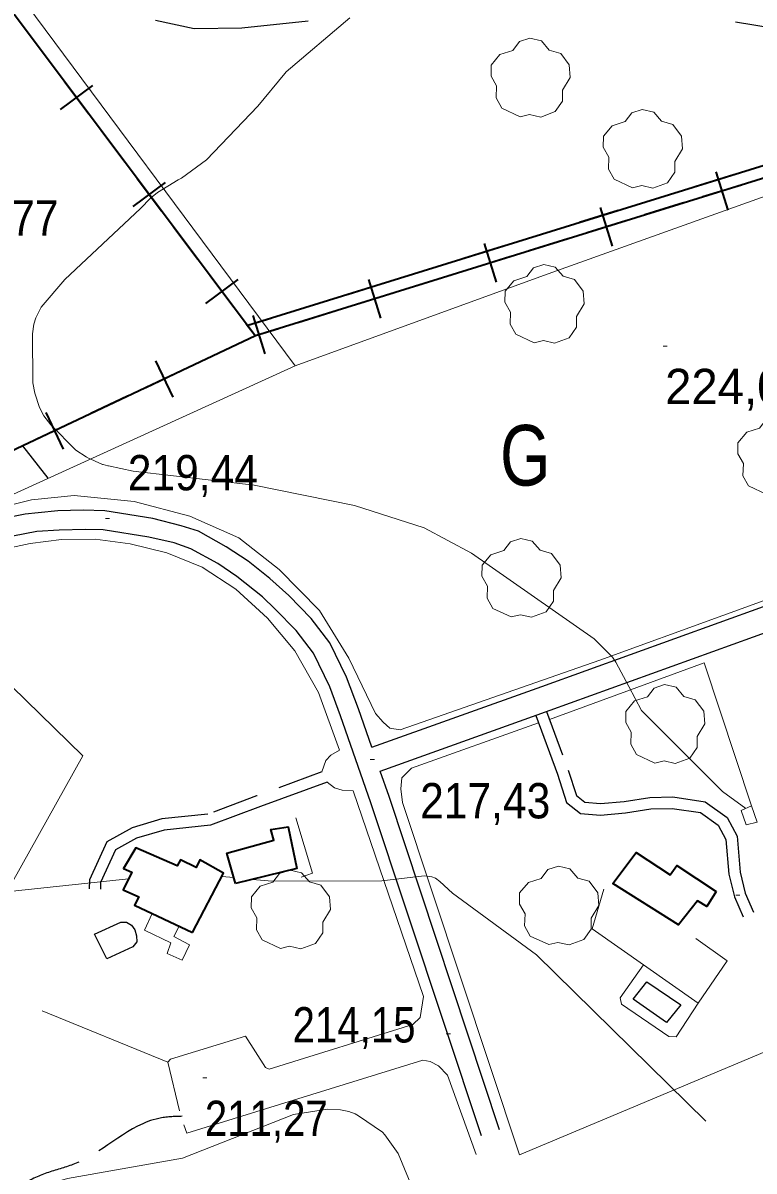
# Model space of a CAD drawing. Extents: x 480269 to 484877, y 4383588 to 4386804.
# Drawn here: x 482664.5 to 482845.4, y 4384938.2 to 4385222.5 of the extents above; entities that cross this region are included whole.
import ezdxf
from ezdxf.enums import TextEntityAlignment as Align

# ---------------------------------------------------------------- set-up
doc = ezdxf.new("R2010")
doc.units = 0
doc.header["$LTSCALE"] = 3.8
doc.linetypes.add('LONG_DASHED', pattern=[7.5, 6, -1.5])
doc.linetypes.add('MEDIUM_DASHED', pattern=[4.5, 3, -1.5])
for name, color, linetype, lineweight in [('21', 7, 'Continuous', 25), ('25', 7, 'LONG_DASHED', 25), ('27', 7, 'Continuous', 25), ('29', 7, 'Continuous', 13), ('34', 7, 'Continuous', 35), ('37', 7, 'Continuous', 25), ('38', 7, 'Continuous', 25), ('47', 7, 'Continuous', 35), ('51', 7, 'Continuous', 13), ('7', 7, 'Continuous', 13), ('9', 7, 'Continuous', 13)]:
    doc.layers.add(name, color=color, linetype=linetype, lineweight=lineweight)
doc.layers.add('31', color=7, linetype='Continuous')

msp = doc.modelspace()

# ---------------------------------------------------------------- linework, layer by layer
at = {"layer": '21'}
for points in [[(482685.28, 4384990.76), (482682.2, 4384996.9), (482688.72, 4384999.82), (482690.15, 4384999.83), (482691.37, 4384999.12), (482692.2, 4384997.92), (482692.63, 4384996.44), (482692.69, 4384995), (482691.71, 4384993.76), (482691.67, 4384993.76)], [(482815.5, 4384980.83), (482818.82, 4384985.11), (482827.28, 4384979.37), (482823.72, 4384975.04)]]:
    msp.add_lwpolyline(points, close=True, dxfattribs=at)
at = {"layer": '25'}
msp.add_lwpolyline([(482586.91, 4385220.21), (482629.4, 4385162.78), (482670.68, 4385109.75)], dxfattribs=at)
at = {"layer": '27'}
msp.add_spline([(482987.06, 4385196.22), (482962.01, 4385203.27), (482933.82, 4385208.75), (482918.16, 4385210.32), (482910.33, 4385217.37), (482911.12, 4385227.55), (482911.12, 4385236.17), (482900.16, 4385244), (482857.87, 4385258.89), (482836.73, 4385270.64), (482824.21, 4385265.15), (482832.82, 4385247.14), (482820.29, 4385239.3), (482767.05, 4385239.3), (482715.37, 4385240.87), (482694.23, 4385249.49), (482675.44, 4385265.94), (482679.36, 4385287.09), (482678.57, 4385302.75), (482650.39, 4385311.37), (482636.29, 4385330.17), (482633.95, 4385351.32), (482617.5, 4385368.55), (482588.53, 4385379.52), (482572.87, 4385393.62), (482558.78, 4385411.63), (482539.21, 4385429.65), (482525.9, 4385448.45), (482516.5, 4385468.82), (482492.23, 4385501.72), (482482.83, 4385522.08), (482488.31, 4385537.75), (482533.73, 4385569.87), (482542.34, 4385576.13)], degree=3, dxfattribs=at)
at = {"layer": '29'}
for points in [[(482787.53, 4385199.25), (482782.99, 4385201.37), (482781.58, 4385203.91), (482781.68, 4385206.89), (482780.31, 4385209.3), (482780.35, 4385212.05), (482782.51, 4385214.65), (482785.7, 4385215.65), (482787.35, 4385217.84), (482789.92, 4385218.67), (482792.78, 4385218.02), (482794.73, 4385215.75), (482797.54, 4385214.93), (482799.67, 4385212.08), (482799.91, 4385208.95), (482798.03, 4385205.8), (482798.03, 4385203.12), (482796.21, 4385200.51), (482792.59, 4385199.17), (482789.82, 4385199.8)], [(482815.31, 4385181.64), (482810.77, 4385183.76), (482809.36, 4385186.3), (482809.46, 4385189.28), (482808.09, 4385191.69), (482808.13, 4385194.44), (482810.29, 4385197.04), (482813.48, 4385198.04), (482815.13, 4385200.23), (482817.7, 4385201.06), (482820.56, 4385200.41), (482822.51, 4385198.14), (482825.32, 4385197.32), (482827.45, 4385194.47), (482827.69, 4385191.34), (482825.81, 4385188.19), (482825.81, 4385185.51), (482823.99, 4385182.9), (482820.37, 4385181.56), (482817.6, 4385182.19)], [(482790.96, 4385143.27), (482786.42, 4385145.39), (482785.01, 4385147.93), (482785.11, 4385150.91), (482783.74, 4385153.32), (482783.78, 4385156.07), (482785.94, 4385158.67), (482789.13, 4385159.67), (482790.78, 4385161.86), (482793.35, 4385162.69), (482796.21, 4385162.04), (482798.16, 4385159.77), (482800.97, 4385158.95), (482803.1, 4385156.1), (482803.34, 4385152.97), (482801.46, 4385149.82), (482801.46, 4385147.14), (482799.64, 4385144.53), (482796.02, 4385143.19), (482793.25, 4385143.82)], [(482848.58, 4385105.73), (482844.04, 4385107.85), (482842.63, 4385110.39), (482842.73, 4385113.37), (482841.36, 4385115.78), (482841.4, 4385118.53), (482843.56, 4385121.13), (482846.75, 4385122.13), (482848.4, 4385124.32), (482850.97, 4385125.15), (482853.83, 4385124.5), (482855.78, 4385122.23), (482858.59, 4385121.41), (482860.72, 4385118.56), (482860.96, 4385115.43), (482859.08, 4385112.28), (482859.08, 4385109.6), (482857.26, 4385106.99), (482853.64, 4385105.65), (482850.87, 4385106.28)], [(482785.27, 4385075.43), (482780.73, 4385077.55), (482779.32, 4385080.09), (482779.42, 4385083.07), (482778.05, 4385085.48), (482778.09, 4385088.23), (482780.25, 4385090.83), (482783.44, 4385091.83), (482785.09, 4385094.02), (482787.66, 4385094.85), (482790.52, 4385094.2), (482792.47, 4385091.93), (482795.28, 4385091.11), (482797.41, 4385088.26), (482797.65, 4385085.13), (482795.77, 4385081.98), (482795.77, 4385079.3), (482793.95, 4385076.69), (482790.33, 4385075.35), (482787.56, 4385075.98)], [(482820.84, 4385039.24), (482816.3, 4385041.36), (482814.89, 4385043.9), (482814.99, 4385046.88), (482813.62, 4385049.29), (482813.66, 4385052.04), (482815.82, 4385054.64), (482819.01, 4385055.64), (482820.66, 4385057.83), (482823.23, 4385058.66), (482826.09, 4385058.01), (482828.04, 4385055.74), (482830.85, 4385054.92), (482832.98, 4385052.07), (482833.22, 4385048.94), (482831.34, 4385045.79), (482831.34, 4385043.11), (482829.52, 4385040.5), (482825.9, 4385039.16), (482823.13, 4385039.79)], [(482794.57, 4384994.29), (482790.03, 4384996.41), (482788.62, 4384998.95), (482788.72, 4385001.93), (482787.35, 4385004.34), (482787.39, 4385007.09), (482789.55, 4385009.69), (482792.74, 4385010.69), (482794.39, 4385012.88), (482796.96, 4385013.71), (482799.82, 4385013.06), (482801.77, 4385010.79), (482804.58, 4385009.97), (482806.71, 4385007.12), (482806.95, 4385003.99), (482805.07, 4385000.84), (482805.07, 4384998.16), (482803.25, 4384995.55), (482799.63, 4384994.21), (482796.86, 4384994.84)], [(482728.19, 4384993.33), (482723.65, 4384995.45), (482722.24, 4384997.99), (482722.34, 4385000.97), (482720.97, 4385003.38), (482721.01, 4385006.13), (482723.17, 4385008.73), (482726.36, 4385009.73), (482728.01, 4385011.92), (482730.58, 4385012.75), (482733.44, 4385012.1), (482735.39, 4385009.83), (482738.2, 4385009.01), (482740.33, 4385006.16), (482740.57, 4385003.03), (482738.69, 4384999.88), (482738.69, 4384997.2), (482736.87, 4384994.59), (482733.25, 4384993.25), (482730.48, 4384993.88)]]:
    msp.add_lwpolyline(points, close=True, dxfattribs=at)
at = {"layer": '34'}
for p, q in [((482665.77, 4385220.01), (482671.77, 4385212.01)), ((482673.76, 4385201.01), (482681.77, 4385207)), ((482674.77, 4385208), (482680.76, 4385200)), ((482683.76, 4385196), (482689.76, 4385188)), ((482692.76, 4385184), (482698.76, 4385176)), ((482840.39, 4385184.9), (482830.84, 4385181.94)), ((482840.39, 4385184.9), (482830.84, 4385181.94)), ((482838.98, 4385176.1), (482836.01, 4385185.65)), ((482691.76, 4385177), (482699.76, 4385183)), ((482842.27, 4385182.35), (482832.72, 4385179.39)), ((482827.95, 4385177.91), (482818.4, 4385174.94)), ((482811.75, 4385176.01), (482802.2, 4385173.04)), ((482811.75, 4385176.01), (482802.2, 4385173.04)), ((482810.34, 4385167.2), (482807.37, 4385176.75)), ((482813.63, 4385173.46), (482804.08, 4385170.49)), ((482701.76, 4385172), (482707.76, 4385164)), ((482783.11, 4385167.11), (482773.56, 4385164.15)), ((482783.11, 4385167.11), (482773.56, 4385164.15)), ((482781.7, 4385158.31), (482778.73, 4385167.86)), ((482799.31, 4385169.01), (482789.76, 4385166.04)), ((482784.99, 4385164.56), (482775.44, 4385161.6)), ((482709.75, 4385153), (482717.76, 4385159)), ((482710.76, 4385160), (482716.75, 4385152)), ((482754.47, 4385158.22), (482744.92, 4385155.25)), ((482754.47, 4385158.22), (482744.92, 4385155.25)), ((482753.06, 4385149.41), (482750.09, 4385158.96)), ((482770.67, 4385160.11), (482761.12, 4385157.15)), ((482756.35, 4385155.67), (482746.8, 4385152.7)), ((482725.83, 4385149.32), (482720.12, 4385147.55)), ((482725.83, 4385149.32), (482720.12, 4385147.55)), ((482724.42, 4385140.52), (482721.45, 4385150.07)), ((482742.03, 4385151.22), (482732.48, 4385148.25)), ((482719.75, 4385148), (482722, 4385145)), ((482727.71, 4385146.77), (482722, 4385145)), ((482717.48, 4385142.86), (482708.44, 4385138.59)), ((482697.26, 4385138.83), (482701.54, 4385129.79)), ((482703.92, 4385136.45), (482694.88, 4385132.18)), ((482690.36, 4385130.04), (482681.32, 4385125.77)), ((482670.14, 4385126.01), (482674.41, 4385116.97)), ((482676.8, 4385123.63), (482667.76, 4385119.35))]:
    msp.add_line(p, q, dxfattribs=at)
for points in [[(481732.67, 4386453.74), (481770, 4386403), (482108, 4385964), (482722, 4385145)], [(483464.12, 4384844.55), (483013.12, 4385238.55), (482720.12, 4385147.55)], [(483464.12, 4384844.55), (483013.12, 4385238.55), (482720.12, 4385147.55)], [(483466, 4384842), (483015, 4385236), (482722, 4385145)], [(482722, 4385145), (482428, 4385006), (482209, 4384913), (481448, 4384699), (481251, 4384637), (481013, 4384577), (480976, 4384524), (480944, 4384410), (480887.47, 4384143.52)]]:
    msp.add_lwpolyline(points, dxfattribs=at)
at = {"layer": '37'}
for points in [[(482750.83, 4385043.15), (482792.84, 4385058.2), (482913.56, 4385101.78), (482939.57, 4385111.12), (482955.6, 4385115), (482967.37, 4385116.08), (482975.61, 4385116.03), (482978.44, 4385115.95), (482985.74, 4385115.14), (482992.89, 4385114), (482999.97, 4385112.36), (483004.37, 4385110.93), (483011.65, 4385108.69), (483016.47, 4385106.74), (483023.56, 4385103.12), (483028.35, 4385099.96), (483040.15, 4385090.7), (483056.73, 4385076.2), (483085.09, 4385052.01)], [(482752.89, 4385037.24), (482794.96, 4385052.31), (482915.68, 4385095.89), (482941.37, 4385105.12), (482956.63, 4385108.81), (482967.62, 4385109.83), (482975.06, 4385109.91), (482977.98, 4385109.7), (482985.07, 4385109.02), (482991.66, 4385107.85), (483002.53, 4385104.94), (483013.88, 4385101.02), (483019.88, 4385097.89), (483024.85, 4385094.76), (483036.16, 4385085.88), (483052.64, 4385071.47), (483081.03, 4385047.25)], [(482750.83, 4385043.15), (482747.52, 4385052.71), (482744.53, 4385060.52), (482740.43, 4385068.99), (482735.77, 4385075.02), (482730.27, 4385080.73), (482725.6, 4385084.97), (482720.22, 4385089.27), (482714.78, 4385092.76), (482707.89, 4385096.67), (482703.64, 4385097.96), (482696.65, 4385099.78), (482684.74, 4385101.71), (482679.41, 4385101.85), (482673.14, 4385101.65), (482668.27, 4385101.21), (482665.02, 4385100.88), (482660.89, 4385100.07)], [(482777.93, 4384946.98), (482750.57, 4385029.42), (482743.09, 4385050.98), (482740.42, 4385058.13), (482736.37, 4385066.43), (482732.09, 4385072.09), (482726.92, 4385077.35), (482723.76, 4385080.43), (482717.45, 4385085.4), (482712.73, 4385088.65), (482706, 4385092.27), (482701.91, 4385093.74), (482695.63, 4385095.13), (482684.37, 4385096.96), (482679.95, 4385097.09), (482673.46, 4385096.91), (482667.94, 4385096.55), (482662.02, 4385095.42)], [(482782.44, 4384948.48), (482755.07, 4385030.94), (482752.89, 4385037.24)]]:
    msp.add_lwpolyline(points, dxfattribs=at)
at = {"layer": '38'}
for points in [[(482888.85, 4385225.44), (482873.65, 4385220.93), (482858.45, 4385219.79), (482840.77, 4385222.66)], [(482735.08, 4385222.93), (482718.69, 4385221.15), (482706.82, 4385220.99), (482697.27, 4385223.12)], [(482791.36, 4385051.02), (482796.74, 4385036.53), (482798.97, 4385029.5), (482802.43, 4385026.8), (482807.39, 4385026.35), (482813.59, 4385026.89), (482819.82, 4385027.92), (482825.14, 4385028), (482832.17, 4385026.97), (482836.51, 4385023.87), (482838.43, 4385020.34), (482839.13, 4385011.77), (482840.51, 4385006.09), (482842.65, 4385001.21)], [(482739.79, 4385034.55), (482723.28, 4385028.5), (482710.87, 4385023.85), (482699.4, 4385022.64), (482692.62, 4385020.62), (482687.39, 4385017.73), (482683.71, 4385009.65), (482683.65, 4385008.04)]]:
    msp.add_lwpolyline(points, dxfattribs=at)
at = {"layer": '38', "linetype": 'MEDIUM_DASHED'}
for points in [[(482794.03, 4385051.98), (482799.43, 4385037.46), (482801.42, 4385031.2), (482803.52, 4385029.55), (482807.39, 4385029.2), (482813.24, 4385029.71), (482819.56, 4385030.75), (482825.32, 4385030.85), (482833.26, 4385029.68), (482838.7, 4385025.8), (482841.21, 4385021.17), (482841.95, 4385012.22), (482843.21, 4385007), (482845.25, 4385002.36)], [(482738.47, 4385037.05), (482722.31, 4385031.13), (482710.22, 4385026.59), (482698.85, 4385025.4), (482691.53, 4385023.22), (482685.22, 4385019.73), (482680.93, 4385010.3), (482680.85, 4385008.14)]]:
    msp.add_lwpolyline(points, dxfattribs=at)
at = {"layer": '38', "linetype": 'LONG_DASHED'}
msp.add_spline([(482703.9, 4384951.8), (482698.11, 4384951.28), (482678.04, 4384940.33), (482671.68, 4384938.18), (482665.31, 4384935.39), (482661.35, 4384932.1), (482655.82, 4384925.86), (482650.14, 4384918.86), (482644.15, 4384906.93), (482643.07, 4384904.68), (482639.1, 4384898.05), (482634.64, 4384889.99), (482631.91, 4384884.65), (482627.67, 4384878.99), (482625.53, 4384876.32)], degree=3, dxfattribs=at)
at = {"layer": '47', "lineweight": 13}
msp.add_lwpolyline([(482846.12, 4385024.59), (482843.4, 4385023.99), (482842.23, 4385027.51), (482844.76, 4385028.62)], close=True, dxfattribs=at)
at = {"layer": '47'}
for points in [[(482717.11, 4385009.39), (482714.93, 4385016.95), (482726.56, 4385020.2), (482725.83, 4385022.78), (482730.09, 4385023.44), (482732.24, 4385013.14)], [(482706.48, 4384997.26), (482714.08, 4385011.96), (482708.27, 4385015.29), (482707.38, 4385013.42), (482703.45, 4385015.33), (482702.64, 4385013.81), (482692.46, 4385018.22), (482689.35, 4385013.14), (482691.44, 4385012.27), (482689.27, 4385007.9), (482693.13, 4385006.14), (482692.11, 4385004.08)], [(482836.04, 4385007.46), (482833.66, 4385003.72), (482831.36, 4385005.13), (482826.66, 4384999.16), (482810.44, 4385009.47), (482816.22, 4385017.11), (482824.61, 4385011.61), (482826.3, 4385013.89)]]:
    msp.add_lwpolyline(points, close=True, dxfattribs=at)
at = {"layer": '51'}
msp.add_line((482700.32, 4384965.17), (482669.22, 4384977.94), dxfattribs=at)
for points in [[(482404.1, 4385677.73), (482302.92, 4385714.75), (482302.94, 4385713.84), (482359.86, 4385638.29), (482423.37, 4385556.01), (482487.7, 4385471.02), (482548.28, 4385389.71), (482609.6, 4385302.12), (482658.45, 4385236.36), (482731.86, 4385137.6), (482793.32, 4385159.98), (482893.05, 4385195.69), (482991.91, 4385230.66), (483071.52, 4385260.62), (483095.48, 4385269.3)], [(482942.5, 4385213.18), (482977.38, 4385117.59), (482963.03, 4385117.44), (482951.62, 4385115.72), (482942.17, 4385113.17), (482923.87, 4385106.77), (482898.56, 4385097.91), (482807.23, 4385064.72), (482757.84, 4385047.5), (482755.28, 4385047.9), (482753.59, 4385049.34), (482751.71, 4385051.55), (482745.16, 4385065.2), (482737.85, 4385077), (482727.91, 4385087.2), (482717.9, 4385095.04), (482705.8, 4385100.41), (482691.98, 4385104.02), (482677.18, 4385105.47), (482666.61, 4385104.38), (482649.93, 4385100.31), (482731.86, 4385137.6)], [(482738.47, 4385037.05), (482739.42, 4385039.88), (482740.69, 4385041.24), (482742.85, 4385042.4), (482737.61, 4385056.68), (482731.73, 4385067.03), (482724.98, 4385075.1), (482717.14, 4385082.31), (482708.84, 4385087.77), (482700.06, 4385091.3), (482691.02, 4385093.51), (482682.36, 4385094.64), (482674.01, 4385094.58), (482666.31, 4385093.62), (482658.93, 4385092.06)], [(482637.01, 4385082.27), (482679.29, 4385041.06), (482648.64, 4384986.12), (482603.01, 4384903.74), (482627.65, 4384884.94)], [(482844.76, 4385028.62), (482833.04, 4385064.09), (482794.76, 4385050.01)], [(482792.04, 4385049.2), (482760.65, 4385037.97), (482758.22, 4385035.58), (482757.98, 4385032.85), (482758.41, 4385029.52), (482787.36, 4384942.24), (482862.97, 4384974.04), (482897.59, 4384990.73)], [(482739.79, 4385034.55), (482741.6, 4385033.08), (482743.47, 4385032.52), (482746.2, 4385032.34), (482763.58, 4384981.45), (482762.74, 4384976.28), (482760.97, 4384974.5), (482725.44, 4384963.48), (482724.49, 4384963.89), (482719.58, 4384971.63), (482700.98, 4384965.91), (482700.32, 4384965.17), (482703.22, 4384953.14)], [(482733.34, 4385010.98), (482736.17, 4385011.98), (482732.04, 4385025.71)], [(482808.18, 4385008.03), (482805.29, 4384998.23), (482831.59, 4384979.78), (482838.72, 4384990.3), (482830.99, 4384995.81)], [(482696.46, 4385002.03), (482694.54, 4384997.9), (482701.06, 4384994.78), (482700.21, 4384992.12), (482703.87, 4384990.48), (482705.68, 4384994.21), (482701.86, 4384996.33), (482703.16, 4384998.85)], [(482831.59, 4384979.78), (482826.11, 4384971.45), (482824.28, 4384971.56), (482812.58, 4384979.52), (482812.24, 4384981.12), (482817.99, 4384989.33)], [(482704.3, 4384949.72), (482705.04, 4384947.6), (482763.46, 4384965.68), (482765.28, 4384965.35), (482767.33, 4384964.26), (482769.57, 4384961.94), (482776.6, 4384942.3)]]:
    msp.add_lwpolyline(points, dxfattribs=at)
at = {"layer": '7'}
for p, q in [((482822.88, 4385142.47), (482823.88, 4385142.47)), ((482684.88, 4385099.76), (482685.88, 4385099.76)), ((482750.44, 4385040.1), (482751.44, 4385040.1)), ((482840.84, 4385006.52), (482841.84, 4385006.52)), ((482769.24, 4384972.2), (482770.24, 4384972.2)), ((482709, 4384961.29), (482710, 4384961.29))]:
    msp.add_line(p, q, dxfattribs=at)
at = {"layer": '9'}
msp.add_line((482716.68, 4385010.89), (482713.67, 4385011.17), dxfattribs=at)
for points in [[(482745.38, 4385223.78), (482729.66, 4385210.38), (482729.26, 4385209.97), (482722.6, 4385201.86), (482709.9, 4385188.57), (482703.74, 4385184.06), (482702.9, 4385183.66), (482697.8, 4385180.5), (482696.09, 4385179.12), (482693.56, 4385176.56), (482674.84, 4385158.98), (482668.99, 4385152.07), (482667.69, 4385149.46), (482667.21, 4385147.91), (482666.84, 4385145.5), (482666.85, 4385145.47), (482666.96, 4385133.39), (482667.4, 4385130.82), (482668.58, 4385127.24), (482669.66, 4385125.17), (482671.37, 4385122.94), (482677.6, 4385116.74), (482680.16, 4385115.04), (482680.2, 4385115.03), (482680.19, 4385115.01), (482680.39, 4385114.88), (482684.17, 4385113.15), (482684.37, 4385113.13), (482685.51, 4385112.82), (482685.65, 4385112.81), (482691.75, 4385111.5), (482721.7, 4385108.06), (482746.55, 4385102.99), (482763.76, 4385097.48), (482775.47, 4385091.19), (482805.86, 4385070), (482810.34, 4385065.45), (482811.19, 4385064.25), (482814.36, 4385058.21), (482817.56, 4385052.22), (482817.57, 4385052.22), (482817.58, 4385052.21), (482817.59, 4385052.17), (482837.56, 4385032.22), (482843.35, 4385028)], [(482690.6, 4385010.58), (482419.98, 4384981.77), (482413.07, 4384980.04), (482412.07, 4384979.99), (482410.45, 4384980.16), (482410.06, 4384980.26), (482409.47, 4384980.51), (482408.75, 4384981.11), (482404.45, 4384986.51), (482401.97, 4384991.54), (482401.63, 4384992.44), (482401.35, 4384993.57), (482401.17, 4384995.59), (482401.44, 4384998.74), (482402.06, 4385001.67), (482409.46, 4385018.27), (482422.79, 4385037.83), (482440.13, 4385058.37), (482441.91, 4385061.5), (482442.78, 4385063.75), (482448.03, 4385113.47), (482452.81, 4385131.35)], [(482833.48, 4384950.6), (482791.55, 4384991.74), (482770.78, 4385007.03), (482767.65, 4385009.9), (482766.56, 4385010.74), (482765.69, 4385011.08), (482765.07, 4385011.2), (482763.74, 4385011.3), (482753.33, 4385010.12), (482726.11, 4385010), (482721.38, 4385010.45)], [(482663.67, 4384934.68), (482667.28, 4384934.59), (482669.81, 4384934.79), (482675.56, 4384936.4), (482704, 4384941.43), (482731.46, 4384952.28), (482739.86, 4384953.56), (482743.07, 4384953.41), (482745.12, 4384952.97), (482746.66, 4384952.37), (482747.55, 4384951.88), (482753.43, 4384947.88), (482754.05, 4384947.19), (482757.31, 4384942.62), (482764.01, 4384926.42), (482778.42, 4384925.89)]]:
    msp.add_lwpolyline(points, dxfattribs=at)

# ---------------------------------------------------------------- texts
at = {"layer": '31', "width": 0.8}
msp.add_text('G', height=15, dxfattribs=at).set_placement((482788.78, 4385107.94), align=Align.CENTER)
at = {"layer": '7'}
for s, width, p in [('217,77', 0.9, (482641.08, 4385169.85)), ('219,44', 0.9, (482690.44, 4385106.76)), ('217,43', 0.9, (482762.76, 4385025.55)), ('214,15', 0.85, (482731.21, 4384970.07)), ('211,27', 0.85, (482709.5, 4384946.92))]:
    msp.add_text(s, height=8.75, dxfattribs=dict(at, width=width)).set_placement(p)
msp.add_text('224,06', height=8.75, dxfattribs=at).set_placement((482823.38, 4385128.1))

doc.saveas('drawing.dxf')
